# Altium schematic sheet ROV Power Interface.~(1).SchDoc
size A
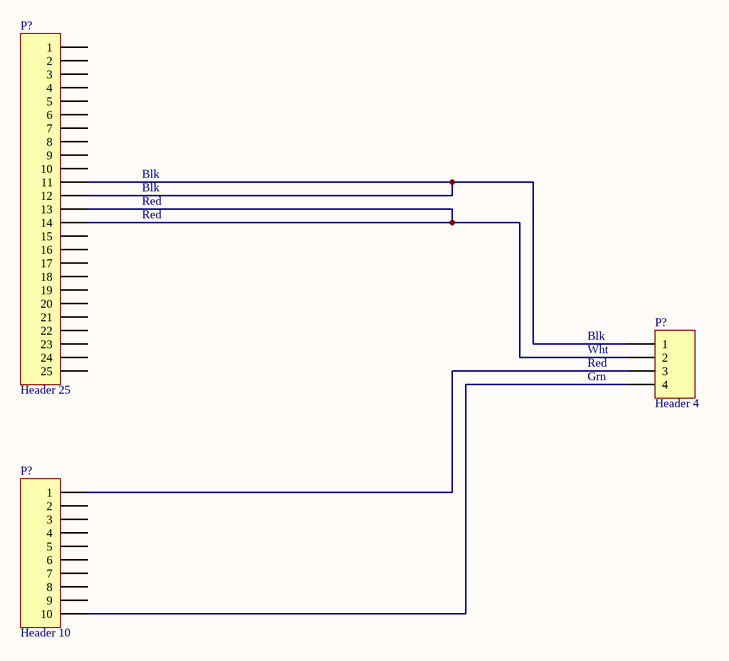
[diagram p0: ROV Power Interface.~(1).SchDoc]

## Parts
(Parts that share a designator on the sheet are numbered #1, #2 ... from top to bottom, then left to right.)
P?#1  Header 25  [HDR1X25]
P?#2  Header 4  [HDR1X4]
P?#3  Header 10  [HDR1X10]

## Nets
NetP?#1_11: P?#1.11 P?#1.12 P?#2.1
NetP?#1_13: P?#1.13 P?#1.14 P?#2.2
NetP?#2_3: P?#2.3 P?#3.1
NetP?#2_4: P?#2.4 P?#3.10

Not connected (* = marked no-connect by the designer): P?#1 1 2 3 4 5 6 7 8 9 10 15 16 17 18 19 20 21 22 23 24 25; P?#3 2 3 4 5 6 7 8 9

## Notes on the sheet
- Blk
- Red
- (near P?#2) Blk
- (near P?#2) Wht
- (near P?#2) Red
- (near P?#2) Grn

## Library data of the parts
P?#1 = Header 25: Header, 25-Pin
P?#2 = Header 4: Header, 4-Pin
P?#3 = Header 10: Header, 10-Pin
